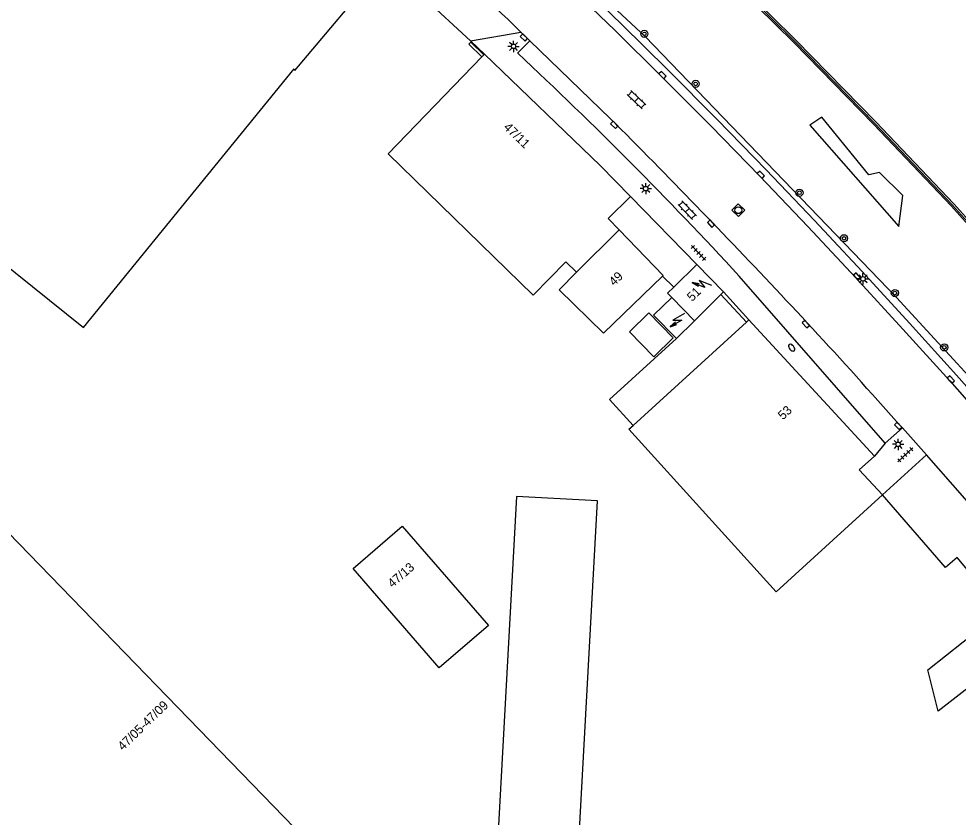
# Model space of a CAD drawing. Extents: x 132999 to 136000, y 398499 to 400501.
# Drawn here: x 134508.4 to 134612.5, y 398629.3 to 398717.8 of the extents above; entities that cross this region are included whole.
import ezdxf

# ---------------------------------------------------------------- set-up
doc = ezdxf.new("R2010")
doc.units = 0
for name, color, linetype in [('gg-afsc-hekwerk', 7, 'Continuous'), ('gg-afsc-muur', 7, 'Continuous'), ('gg-anno-huisnummerreeks BGT', 7, 'Continuous'), ('gg-bbg-bijgebouw', 7, 'Continuous'), ('gg-bbg-gedigitaliseerde bebouwing', 7, 'Continuous'), ('gg-bbg-gedigitaliseerde bijgebouw', 7, 'Continuous'), ('gg-bbg-hoofdgebouw', 7, 'Continuous'), ('gg-bbg-luifel en loopbrug', 7, 'Continuous'), ('gg-bbg-tussenscheiding', 7, 'Continuous'), ('gg-knt-bronhoudergrens', 7, 'Continuous'), ('gg-knt-verharding', 7, 'Continuous'), ('gg-knt-verharding nz', 7, 'Continuous'), ('gt-grn-groengrens', 7, 'Continuous'), ('gt-grn-weggrens', 7, 'Continuous'), ('gt-symb-boom', 7, 'Continuous'), ('gt-symb-brandkraan', 7, 'Continuous'), ('gt-symb-klinker verharding', 7, 'Continuous'), ('gt-symb-kolk', 7, 'Continuous'), ('gt-symb-lichtmast', 7, 'Continuous'), ('gt-symb-rioolschacht', 7, 'Continuous'), ('gt-symb-tegel verharding', 7, 'Continuous'), ('gt-symb-trafo symbool', 7, 'Continuous'), ('gx-grn-maaiveld', 7, 'Continuous')]:
    doc.layers.add(name, color=color, linetype=linetype)

# ---------------------------------------------------------------- blocks, each defined once
blk = doc.blocks.new('gt0-BOOM')
at = {"layer": 'gt-symb-boom'}
for radius in [0.4, 0.2]:
    blk.add_circle((0, 0), radius, dxfattribs=at)
blk = doc.blocks.new('gt0-HSP')
at = {"layer": 'gt-symb-trafo symbool'}
for points in [[(0.77, 0.75), (-0.53, 0), (0.47, 0), (-0.83, -0.75)], [(-0.22, -0.24), (-0.83, -0.75), (-0.08, -0.48)]]:
    blk.add_lwpolyline(points, dxfattribs=at)
blk = doc.blocks.new('gt0-LMAST')
at = {"layer": 'gt-symb-lichtmast'}
for p, q in [((-0.18, 0.17), (-0.45, 0.44)), ((-0.01, 0.25), (-0.01, 0.62)), ((0.17, 0.17), (0.44, 0.44)), ((-0.26, 0), (-0.63, 0)), ((-0.18, -0.18), (-0.45, -0.45)), ((-0.01, -0.25), (-0.01, -0.63)), ((0.44, -0.45), (0.17, -0.18)), ((0.24, 0), (0.62, 0))]:
    blk.add_line(p, q, dxfattribs=at)
blk.add_circle((-0.01, 0), 0.25, dxfattribs=at)
blk = doc.blocks.new('gt0-KOLK')
at = {"layer": 'gt-symb-kolk'}
blk.add_lwpolyline([(0, 0), (0.37, 0), (0.37, 0.4), (-0.38, 0.4), (-0.38, 0), (0, 0)], dxfattribs=at)
blk = doc.blocks.new('gt0-TEG1')
at = {"layer": 'gt-symb-tegel verharding'}
for p, q in [((-1.12, 0), (1.12, 0)), ((-0.9, -0.25), (-0.9, 0.25)), ((-0.45, -0.25), (-0.45, 0.25)), ((0, -0.25), (0, 0.25)), ((0.45, -0.25), (0.45, 0.25)), ((0.9, -0.25), (0.9, 0.25))]:
    blk.add_line(p, q, dxfattribs=at)
blk = doc.blocks.new('gt0-BR')
at = {"layer": 'gt-symb-brandkraan'}
for centre, radius, start, end in [((-0.24, 0), 0.206, 107.5669, 252.4331), ((0.6, -2.66), 3, 106.892, 107.5669), ((0, -0.69), 0.938, 73.108, 106.892), ((-0.6, -2.66), 3, 72.4331, 73.108), ((0.24, 0), 0.206, 287.567, 72.4331), ((0.6, 2.66), 3, 252.4331, 253.108), ((0, 0.69), 0.938, 253.108, 286.8921), ((-0.6, 2.66), 3, 286.8921, 287.567)]:
    blk.add_arc(centre, radius, start, end, dxfattribs=at)
blk = doc.blocks.new('gt0-KL1')
at = {"layer": 'gt-symb-klinker verharding'}
for p, q in [((-1.15, 0.3), (1.15, 0.3)), ((-1, -0.3), (-1, 0.3)), ((-0.5, 0.3), (-0.5, 0.45)), ((0, -0.3), (0, 0.3)), ((0.5, 0.3), (0.5, 0.45)), ((1, -0.3), (1, 0.3)), ((-1.15, -0.3), (1.15, -0.3)), ((-0.5, -0.45), (-0.5, -0.3)), ((0.5, -0.45), (0.5, -0.3))]:
    blk.add_line(p, q, dxfattribs=at)
blk = doc.blocks.new('gt0-RS')
at = {"layer": 'gt-symb-rioolschacht'}
blk.add_lwpolyline([(-0.5, -0.5), (0.5, -0.5), (0.5, 0.5), (-0.5, 0.5)], close=True, dxfattribs=at)
blk.add_circle((0, 0), 0.375, dxfattribs=at)

msp = doc.modelspace()

# ---------------------------------------------------------------- linework, layer by layer
at = {"layer": 'gg-afsc-hekwerk'}
msp.add_lwpolyline([(134617.42, 398652.09), (134612.4, 398658.11), (134611.11, 398656.99), (134604.11, 398665.05)], dxfattribs=at)
at = {"layer": 'gg-afsc-muur'}
for p, q in [((134576.19, 398698.12), (134583.52, 398690.61)), ((134579.74, 398689.32), (134580.98, 398688.08))]:
    msp.add_line(p, q, dxfattribs=at)
for points in [[(134507.72, 398789.99), (134518.92, 398781.56), (134528.8, 398773.87), (134539.66, 398765.16), (134550.3, 398756.19), (134559.84, 398747.95), (134569.22, 398739.53), (134578.43, 398730.94), (134585.64, 398723.98), (134586.21, 398723.41), (134594.39, 398715.33), (134603.24, 398706.28), (134611.89, 398697.19), (134616.53, 398692.01), (134630.3, 398676.49), (134639.35, 398665.82), (134647.82, 398654.64), (134659.64, 398639.07), (134674.13, 398620.13)], [(134559.7, 398713.61), (134558.25, 398715.01), (134558.47, 398715.24), (134559.92, 398713.84)]]:
    msp.add_lwpolyline(points, dxfattribs=at)
at = {"layer": 'gg-bbg-bijgebouw'}
for points in [[(134581.29, 398682.39), (134578.74, 398684.98), (134580.74, 398686.94)], [(134561.09, 398620.32), (134570.09, 398619.81), (134572.53, 398664.39), (134563.53, 398664.88), (134561.09, 398620.32)]]:
    msp.add_lwpolyline(points, dxfattribs=at)
at = {"layer": 'gg-bbg-gedigitaliseerde bebouwing'}
for p, q in [((134559.7, 398713.61), (134559.92, 398713.84)), ((134559.92, 398713.84), (134560, 398713.92)), ((134586.19, 398687.26), (134583.26, 398684.35)), ((134576.46, 398672.76), (134589.03, 398684.2)), ((134583.26, 398684.35), (134581.29, 398682.39)), ((134558.74, 398607.74), (134491.47, 398677.04))]:
    msp.add_line(p, q, dxfattribs=at)
for points in [[(134491.47, 398677.04), (134504.2, 398692.7), (134515.54, 398683.62), (134538.88, 398712.3), (134538.98, 398712.1), (134548.77, 398723.74)], [(134570.2, 398689.75), (134569.01, 398690.9), (134565.38, 398687.18), (134549.3, 398702.88), (134559.7, 398713.61)], [(134573.2, 398682.98), (134568.27, 398687.78), (134570.2, 398689.75)], [(134604.11, 398665.05), (134592.34, 398654.32), (134575.99, 398672.33), (134576.46, 398672.76)], [(134545.43, 398656.89), (134550.88, 398661.6), (134560.42, 398650.58), (134554.98, 398645.87), (134545.43, 398656.89)]]:
    msp.add_lwpolyline(points, dxfattribs=at)
at = {"layer": 'gg-bbg-gedigitaliseerde bijgebouw'}
for points in [[(134580.92, 398682.47), (134578.21, 398685.23), (134576.06, 398683.12), (134578.77, 398680.36), (134580.92, 398682.47)], [(134614.28, 398644.18), (134610.28, 398641.07), (134609.15, 398645.67), (134615.01, 398650.3)]]:
    msp.add_lwpolyline(points, dxfattribs=at)
at = {"layer": 'gg-bbg-hoofdgebouw'}
for p, q in [((134580.98, 398688.08), (134583.52, 398690.61)), ((134583.52, 398690.61), (134586.49, 398687.56)), ((134579.74, 398689.32), (134573.2, 398682.98)), ((134586.49, 398687.56), (134586.19, 398687.26)), ((134589.31, 398684.46), (134589.03, 398684.2)), ((134603.21, 398669.34), (134589.31, 398684.46))]:
    msp.add_line(p, q, dxfattribs=at)
for points in [[(134576.19, 398698.12), (134572.82, 398701.57), (134560, 398713.92)], [(134576.19, 398698.12), (134573.69, 398695.69), (134574.91, 398694.44)], [(134574.91, 398694.44), (134579.81, 398689.39), (134579.74, 398689.32)], [(134580.74, 398686.94), (134580.29, 398687.4), (134580.98, 398688.08)], [(134604.11, 398665.05), (134601.54, 398667.84), (134603.21, 398669.34)]]:
    msp.add_lwpolyline(points, dxfattribs=at)
at = {"layer": 'gg-bbg-luifel en loopbrug'}
msp.add_line((134589.03, 398684.2), (134586.19, 398687.26), dxfattribs=at)
msp.add_lwpolyline([(134581.29, 398682.39), (134573.86, 398675.62), (134576.46, 398672.76)], dxfattribs=at)
at = {"layer": 'gg-bbg-tussenscheiding'}
for p, q in [((134570.2, 398689.75), (134574.91, 398694.44)), ((134580.74, 398686.94), (134583.26, 398684.35))]:
    msp.add_line(p, q, dxfattribs=at)
at = {"layer": 'gg-knt-bronhoudergrens'}
for p, q in [((134559.87, 398732.6), (134577.8, 398715.87)), ((134577.8, 398715.87), (134605.67, 398686.94)), ((134605.67, 398686.94), (134623.05, 398667.95))]:
    msp.add_line(p, q, dxfattribs=at)
at = {"layer": 'gg-knt-verharding'}
for p, q in [((134552.59, 398720.79), (134558.43, 398715.38)), ((134558.43, 398715.38), (134564.02, 398716.35)), ((134565.02, 398715.39), (134564.02, 398716.35)), ((134558.43, 398715.38), (134560, 398713.92)), ((134565.02, 398715.39), (134563.66, 398714.01)), ((134604.4, 398670.78), (134588.24, 398689.32)), ((134586.49, 398687.56), (134589.31, 398684.46)), ((134606.33, 398672.5), (134604.4, 398670.78)), ((134606.33, 398672.5), (134605.97, 398672.84))]:
    msp.add_line(p, q, dxfattribs=at)
for points in [[(134518.26, 398765.56), (134526.11, 398759.36), (134533.9, 398753.09), (134539.83, 398748.14), (134545.7, 398743.1), (134551.51, 398737.99), (134557.25, 398732.8), (134563.29, 398727.22), (134569.27, 398721.57), (134574.46, 398716.54), (134579.6, 398711.45), (134585.08, 398705.95), (134590.5, 398700.4), (134595.85, 398694.79), (134601.14, 398689.13), (134606.38, 398683.43), (134611.58, 398677.68), (134616.71, 398671.86), (134621.78, 398665.99), (134626.76, 398660.1), (134631.67, 398654.15), (134636.53, 398648.1), (134641.34, 398642), (134650.97, 398629.47)], [(134575.11, 398705.6), (134574.52, 398706.22), (134573.92, 398706.78), (134565.02, 398715.39)], [(134585.77, 398694.69), (134585.25, 398695.26), (134584.64, 398695.87)], [(134596.35, 398683.51), (134595.77, 398684.12), (134595.2, 398684.75)]]:
    msp.add_lwpolyline(points, dxfattribs=at)
for centre, radius, start, end in [((134349.56, 398498.5), 305.7, 45.449, 48.4274), ((134244.02, 398371.4), 468.57, 42.7254, 46.9861), ((134081.69, 398213.39), 696.95, 43.80951, 44.92907), ((134036.48, 398164.19), 763.64, 42.97466, 44.00253), ((134120.83, 398244.81), 646.97, 41.42129, 42.69365)]:
    msp.add_arc(centre, radius, start, end, dxfattribs=at)
at = {"layer": 'gg-knt-verharding nz'}
for p, q in [((134609, 398669.51), (134606.33, 398672.5)), ((134604.11, 398665.05), (134609, 398669.51))]:
    msp.add_line(p, q, dxfattribs=at)
msp.add_lwpolyline([(134625.95, 398649.73), (134621.87, 398654.55), (134616.15, 398661.31), (134609, 398669.51)], dxfattribs=at)
at = {"layer": 'gt-grn-groengrens'}
for points in [[(134518.87, 398766.35), (134526.73, 398760.14), (134534.53, 398753.86), (134540.47, 398748.9), (134546.35, 398743.86), (134552.17, 398738.74), (134557.92, 398733.54), (134563.97, 398727.95), (134569.96, 398722.29), (134575.16, 398717.25), (134580.31, 398712.16), (134585.79, 398706.66), (134591.22, 398701.1), (134596.57, 398695.48), (134601.87, 398689.81), (134607.12, 398684.1), (134612.32, 398678.34), (134617.46, 398672.52), (134622.54, 398666.64), (134627.53, 398660.74), (134632.44, 398654.78), (134637.32, 398648.72), (134642.13, 398642.62), (134651.77, 398630.08)], [(134605.94, 398694.82), (134606.35, 398698.24), (134603.77, 398700.79), (134602.58, 398700.53), (134597.4, 398706.94), (134596.05, 398706.06), (134605.94, 398694.82)]]:
    msp.add_lwpolyline(points, dxfattribs=at)
at = {"layer": 'gt-grn-weggrens'}
msp.add_line((134604.4, 398670.78), (134603.21, 398669.34), dxfattribs=at)
at = {"layer": 'gx-grn-maaiveld'}
for points in [[(134674.27, 398620.23), (134659.78, 398639.18), (134647.96, 398654.75), (134639.49, 398665.93), (134630.43, 398676.61), (134616.66, 398692.13), (134612.01, 398697.31), (134603.36, 398706.4), (134594.51, 398715.45), (134586.34, 398723.54), (134585.76, 398724.11), (134578.55, 398731.06), (134569.34, 398739.65), (134559.95, 398748.08), (134550.42, 398756.32), (134539.77, 398765.3), (134528.9, 398774.01), (134519.02, 398781.7), (134507.82, 398790.13)], [(134507.61, 398789.85), (134518.81, 398781.42), (134528.69, 398773.73), (134539.55, 398765.03), (134550.19, 398756.06), (134559.72, 398747.82), (134569.1, 398739.4), (134578.31, 398730.81), (134585.52, 398723.86), (134586.09, 398723.29), (134594.27, 398715.2), (134603.11, 398706.15), (134611.76, 398697.07), (134616.4, 398691.9), (134630.17, 398676.38), (134639.22, 398665.71), (134647.68, 398654.54), (134659.5, 398638.97), (134673.99, 398620.02)]]:
    msp.add_lwpolyline(points, dxfattribs=at)

# ---------------------------------------------------------------- block references
at = {"layer": 'gt-symb-boom'}
for p in [(134577.71, 398716.17), (134583.4, 398710.62), (134594.9, 398698.55), (134599.84, 398693.5), (134605.49, 398687.43), (134610.96, 398681.41)]:
    msp.add_blockref('gt0-BOOM', p, dxfattribs=at)
at = {"layer": 'gt-symb-brandkraan', "rotation": -51.698006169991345}
msp.add_blockref('gt0-BR', (134594.05, 398681.37), dxfattribs=at)
at = {"layer": 'gt-symb-klinker verharding'}
for p, rotation in [((134576.84, 398708.86), -43.703569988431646), ((134582.46, 398696.61), 133.9465895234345)]:
    msp.add_blockref('gt0-KL1', p, dxfattribs=dict(at, rotation=rotation))
at = {"layer": 'gt-symb-kolk'}
for p, rotation in [((134564.49, 398715.9), 136.13442163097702), ((134579.6, 398711.45), -44.83791901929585), ((134574.52, 398706.22), 134.18964697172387), ((134590.5, 398700.4), -46.05341047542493), ((134585.25, 398695.26), 132.36616983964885), ((134601.14, 398689.13), -47.385944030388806), ((134595.77, 398684.12), 133.29864539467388), ((134611.54, 398677.71), -47.94020353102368), ((134605.97, 398672.84), 136.45841765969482)]:
    msp.add_blockref('gt0-KOLK', p, dxfattribs=dict(at, rotation=rotation))
at = {"layer": 'gt-symb-lichtmast'}
for p in [(134563.22, 398714.78), (134577.87, 398699.01), (134601.96, 398689), (134605.85, 398670.66)]:
    msp.add_blockref('gt0-LMAST', p, dxfattribs=at)
at = {"layer": 'gt-symb-rioolschacht', "rotation": -44.55460008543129}
msp.add_blockref('gt0-RS', (134588.13, 398696.61), dxfattribs=at)
at = {"layer": 'gt-symb-tegel verharding'}
for p, rotation in [((134583.71, 398691.88), 133.25692965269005), ((134606.64, 398669.5), -136.94423037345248)]:
    msp.add_blockref('gt0-TEG1', p, dxfattribs=dict(at, rotation=rotation))
at = {"layer": 'gt-symb-trafo symbool', "rotation": -51.98433951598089}
msp.add_blockref('gt0-HSP', (134584.13, 398688.41), dxfattribs=at)
at = {"layer": 'gt-symb-trafo symbool'}
msp.add_blockref('gt0-HSP', (134581.4, 398684.43), dxfattribs=at)

# ---------------------------------------------------------------- texts
at = {"layer": 'gg-anno-huisnummerreeks BGT'}
for s, rotation, p in [('47/11', 316.1, (134562.03, 398705.72)), ('49', 44.2, (134574.36, 398688.15)), ('51', 44.2, (134583.01, 398686.44)), ('53', 42.6, (134593.07, 398673.31)), ('47/13', 40.9, (134549.78, 398654.7)), ('47/05-47/09', 44.1, (134519.9, 398636.65))]:
    msp.add_text(s, height=1, rotation=rotation, dxfattribs=at).set_placement(p)

doc.saveas('drawing.dxf')
